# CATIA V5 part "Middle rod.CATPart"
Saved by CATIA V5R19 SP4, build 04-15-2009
Part number: Middle Rod
Bounding box of the stored display mesh (mm): x 0 to 10, y 0 to 280, z -35 to 5
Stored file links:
  G:\EU_thinkMotion\CFAO_2010\MMS_groupe1\MMS_groupe1\OK\ptangsittisin\TANGSITTISIN\TANGSITTISIN\Middle rod.CATPart
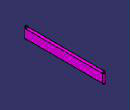
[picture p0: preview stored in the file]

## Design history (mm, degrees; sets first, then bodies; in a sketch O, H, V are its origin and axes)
Body1 (main body)
  Sketch1 on yz-plane, origin (0, 0, 0), H (0, 1, 0), V (0, 0, 1)
    line L1 (0, 0) -> (280, 0)
    line L2 (280, 0) -> (280, -30)
    line L3 (280, -30) -> (0, -30)
    line L4 (0, -30) -> (0, 0)
    length L2 = 30
    length L1 = 280
    perpendicularity: L3 L2, L3 L4
  Pad1: profile Sketch1, direction (1, 0, 0), length 10
  Fillet1: radius 5, on edge [face of Pad1 from Sketch1.L2 | end face of Pad1]; edge [start face of Pad1 | face of Pad1 from Sketch1.L2]; edge [start face of Pad1 | face of Pad1 from Sketch1.L4]; edge [face of Pad1 from Sketch1.L4 | end face of Pad1]
  Sketch2 on face of Pad1 from Sketch1.L3, origin (0, 0, -30), H (1, 0, 0), V (0, -1, 0)
    circle A1 centre (5, -5) radius 2.5
    circle A2 centre (5, -275) radius 2.5
    radius A1 = 2.5
    radius A2 = 2.5
  Pad2: profile Sketch2, direction (0, 0, -1), length 5
  Sketch3 on face of Pad1 from Sketch1.L1, origin (0, 0, 0), H (1, 0, 0), V (0, 1, 0)
    circle A1 centre (5, 275) radius 2.5
    circle A2 centre (5, 5) radius 2.5
    radius A1 = 2.5
    radius A2 = 2.5
  Pad3: profile Sketch3, direction (0, 0, 1), length 5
